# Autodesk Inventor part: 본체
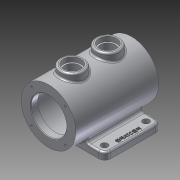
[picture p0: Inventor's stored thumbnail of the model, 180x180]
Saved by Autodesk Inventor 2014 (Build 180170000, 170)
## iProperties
Created: 2014-12
Part Number: 본체
Material: 알루미늄 6061
Document SubType Name: Modeling
Designer: Owner
Density: 2.71 g/cm^3
Appearance: 알루미늄 - 평지
Mass: 1295.77 g
Surface Area: 1031.89 cm^2
Volume: 478.142 cm^3
Author: Owner
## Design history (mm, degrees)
sketch "스케치1"
  geometry: C1 r 46 at (0, 0); 1 further point
  constraints: 1 centre point, 1 coincident
  dimensions: "d0" = 92 diameter of C1
extrude "돌출1" new body sketch "스케치1" stored distance "d1" = 140; taper "d2" = 0 deg
node "작업 평면1"
sketch "스케치2"
  geometry: L1 (-38, 65)-(-50, 65); L2 (-50, 65)-(-50, -65); L3 (-50, -65)-(-38, -65); L4 (-38, 38.884)-(-38, 65); L5 (-38, -38.884)-(-38, -65); A1 r 46 centre (0, 0) between (-38, -25.923) and (-38, 25.923) reference; A2 r 46 centre (0, 0) between (-29.765, -35.072) and (-29.765, 35.072); A3 r 5 centre (-33, 38.884) between (-38, 38.884) and (-29.765, 35.072); A4 r 5 centre (-33, -38.884) between (-29.765, -35.072) and (-38, -38.884); 2 further points
  constraints: 10 end point, 10 point on circle, 4 tangent, 3 centre point, 2 parallel, 2 point on line, 1 coincident, 1 collinear, 1 equal radius, 1 horizontal, 1 horizontal alignment, 1 midpoint, 1 perpendicular
  dimensions: "d4" = 130 distance of L1.end L2.end; "d5" = 50 distance from line of point (0, 0) L2; "d6" = 12 distance of L1.start L1.end; "d7" = 12 distance between parallel lines of L2 L5; "d8" = 5 radius of A3
extrude "돌출2" join sketch "스케치2" distance "d9" = 95; taper "d10" = 0 deg
hole "구멍1" diameter "d13" = 60; stored, may be unused: countersink angle "d17" = 90 deg, drill point angle "d19" = 118 deg; dims "d11" = 10, "d12" = 10, "d14" = 6, "d15" = 4, "d16" = 2, "d18" = 8
node "작업 평면2"
sketch "스케치3"
  geometry: C1 r 37.5 at (0, 0); 1 further point
  constraints: 1 centre point, 1 coincident
  dimensions: "d21" = 75 diameter of C1
extrude "돌출3" cut sketch "스케치3" distance "d22" = 116; taper "d23" = 0 deg
node "작업 평면3"
sketch "스케치4"
  geometry: L1 (-70, 46)-(-70, -46) reference; L2 (70, -46)-(70, 46) reference; C1 r 20 at (-30, 0); C2 r 20 at (30, 0); 1 further point
  constraints: 2 centre point, 2 horizontal alignment
  dimensions: "d25" = 40 diameter of C1; "d27" = 40 distance from line of L1 C1.centre; "d29" = 40 diameter of C2; "d30" = 40 distance from line of L2 C2.centre
extrude "돌출4" join sketch "스케치4" stored distance "d31" = 116; taper "d32" = 0 deg
hole "구멍2" diameter "d35" = 25; stored, may be unused: countersink angle "d39" = 90 deg, drill point angle "d41" = 118 deg; dims "d33" = 10, "d34" = 10, "d36" = 6, "d37" = 30, "d38" = 8, "d40" = 8
hole "구멍3" diameter "d44" = 25; stored, may be unused: countersink angle "d48" = 90 deg, drill point angle "d50" = 118 deg; dims "d42" = 10, "d43" = 10, "d45" = 6, "d46" = 30, "d47" = 8, "d49" = 8
sketch "스케치5"
  geometry: L1 (0, 0)-(26.116, 0) reference; L2 (26.116, -95)-(0, -95) reference; L3 (26.116, 0)-(26.116, -95) reference; 3 further points
  dimensions: "d53" = 13 distance from line of L3 point (13.116, -12.5); "d54" = 12.5 distance from line of L1 point (13.116, -12.5); "d55" = 12.5 distance from line of L2 point (13.116, -82.5); "d56" = 13 distance from line of L3 point (13.116, -82.5)
hole "구멍4" sketch "스케치5" at (13.116, -12.5), (13.116, -82.5) diameter "d57" = 11; stored, may be unused: countersink angle "d61" = 90 deg, drill point angle "d63" = 118 deg; dims "d58" = 6, "d59" = 30, "d60" = 8, "d62" = 8
sketch "스케치6"
  geometry: L1 (26.116, 0)-(26.116, -95) reference; C1 r 5.5 at (13.116, -82.5) reference; 2 further points
  constraints: 1 other
  dimensions: "d64" = 35 vertical distance of C1.centre point (18.116, -47.5); "d65" = 8 distance from line of L1 point (18.116, -47.5)
feature "엠보싱1" sketch "스케치6" dims "d66" = 1, "d67" = 0
fillet "모깎기1" dims "d68" = 10
fillet "모깎기2" dims "d69" = 3
fillet "모깎기3" dims "d70" = 3
fillet "모깎기4" dims "d71" = 3
chamfer "모따기1" distance "d72" = 1; stored, may be unused: second distance "d73" = 2, angle "d74" = 45 deg
chamfer "모따기2" distance "d75" = 1; stored, may be unused: second distance "d76" = 2, angle "d77" = 45 deg
sketch "스케치7"
  geometry: L1 (0, 0)-(28.284, -28.284); L2 (0, 0)-(40, 0); C1 r 31 at (0, 0) reference; 1 further point
  constraints: 4 end point, 1 coincident, 1 equal length, 1 horizontal
  dimensions: "d78" = 40 distance of L1.start L1.end; "d79" = 45 deg angle of L1 L2
hole "구멍5" sketch "스케치7" at (28.284, -28.284) diameter "d80" = 3.242; stored, may be unused: countersink angle "d84" = 90 deg, drill point angle "d86" = 118 deg; dims "d81" = 8, "d82" = 30, "d83" = 8, "d85" = 10
node "솔리드1"
mirror "대칭1"
pattern_circular "원형 패턴1" dims angle "d88" = 360 deg
mirror "대칭2"
other parameters: "d3" = -15, "d20" = -12, "d24" = 56
